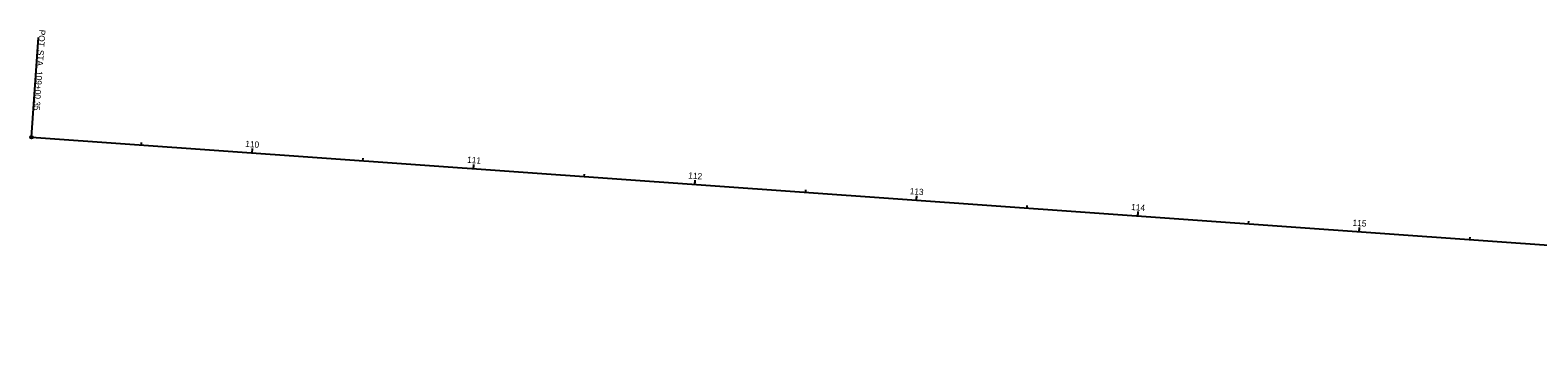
# Model space of a CAD drawing. Extents: x 1898401 to 1901169, y 703131 to 703379.
# Drawn here: x 1898401 to 1899080, y 703230 to 703379 of the extents above; entities that cross this region are included whole.
import ezdxf

# ---------------------------------------------------------------- set-up
doc = ezdxf.new("R2010")
doc.units = 0
for name, color, linetype in [('RW_X_CL', 7, 'Continuous'), ('RW_X_CL_1000_Cardinal_Points', 7, 'Continuous'), ('RW_X_CL_1000_Stations', 7, 'Continuous'), ('RW_X_CL_100_Cardinal_Points', 7, 'Continuous'), ('RW_X_CL_100_Stations', 7, 'Continuous'), ('RW_X_CL_500_Cardinal_Points', 7, 'Continuous'), ('RW_X_CL_500_Stations', 7, 'Continuous')]:
    doc.layers.add(name, color=color, linetype=linetype)

msp = doc.modelspace()

# ---------------------------------------------------------------- linework, layer by layer
at = {"layer": 'RW_X_CL'}
msp.add_line((1898401.58, 703330.4), (1899815.76, 703229.84), dxfattribs=at)
at = {"layer": 'RW_X_CL_1000_Cardinal_Points'}
msp.add_line((1898401.58, 703330.4), (1898404.77, 703375.29), dxfattribs=at)
msp.add_circle((1898401.58, 703330.4), 0.6, dxfattribs=at)
at = {"layer": 'RW_X_CL_1000_Stations'}
for p, q in [((1898500.98, 703323.33), (1898501.12, 703325.33)), ((1898999.72, 703287.87), (1898999.81, 703289.07))]:
    msp.add_line(p, q, dxfattribs=at)
at = {"layer": 'RW_X_CL_100_Cardinal_Points'}
msp.add_line((1898401.58, 703330.4), (1898404.77, 703375.29), dxfattribs=at)
msp.add_circle((1898401.58, 703330.4), 0.6, dxfattribs=at)
at = {"layer": 'RW_X_CL_100_Stations'}
for p, q in [((1898451.11, 703326.88), (1898451.19, 703328.08)), ((1898500.98, 703323.33), (1898501.12, 703325.33)), ((1898550.85, 703319.79), (1898550.94, 703320.98)), ((1898600.73, 703316.24), (1898600.87, 703318.24)), ((1898650.6, 703312.69), (1898650.69, 703313.89)), ((1898700.48, 703309.15), (1898700.62, 703311.14)), ((1898750.35, 703305.6), (1898750.44, 703306.8)), ((1898800.23, 703302.05), (1898800.37, 703304.05)), ((1898850.1, 703298.51), (1898850.18, 703299.7)), ((1898899.97, 703294.96), (1898900.12, 703296.96)), ((1898949.85, 703291.41), (1898949.93, 703292.61)), ((1898999.72, 703287.87), (1898999.86, 703289.86)), ((1899049.6, 703284.32), (1899049.68, 703285.52))]:
    msp.add_line(p, q, dxfattribs=at)
at = {"layer": 'RW_X_CL_500_Cardinal_Points'}
msp.add_line((1898401.58, 703330.4), (1898404.77, 703375.29), dxfattribs=at)
msp.add_circle((1898401.58, 703330.4), 0.6, dxfattribs=at)
at = {"layer": 'RW_X_CL_500_Stations'}
for p, q in [((1898500.98, 703323.33), (1898501.12, 703325.33)), ((1898600.73, 703316.24), (1898600.81, 703317.44)), ((1898700.48, 703309.15), (1898700.56, 703310.34)), ((1898800.23, 703302.05), (1898800.31, 703303.25)), ((1898899.97, 703294.96), (1898900.06, 703296.16)), ((1898999.72, 703287.87), (1898999.86, 703289.86))]:
    msp.add_line(p, q, dxfattribs=at)

# ---------------------------------------------------------------- texts
at = {"layer": 'RW_X_CL_1000_Cardinal_Points'}
for s, p in [('POT', (1898405.08, 703378.92)), (' STA. ', (1898404.51, 703370.89)), ('109+00.35', (1898403.76, 703360.34))]:
    msp.add_text(s, height=2.8, rotation=265.93252, dxfattribs=at).set_placement(p)
at = {"layer": 'RW_X_CL_1000_Stations'}
msp.add_text('110', height=2.8, rotation=355.93252, dxfattribs=at).set_placement((1898497.82, 703326.11))
at = {"layer": 'RW_X_CL_100_Cardinal_Points'}
for s, p in [('POT', (1898405.08, 703378.92)), (' STA. ', (1898404.51, 703370.89)), ('109+00.35', (1898403.76, 703360.34))]:
    msp.add_text(s, height=2.8, rotation=265.93252, dxfattribs=at).set_placement(p)
at = {"layer": 'RW_X_CL_100_Stations'}
for s, p in [('110', (1898497.82, 703326.11)), ('111', (1898597.76, 703318.96)), ('112', (1898697.38, 703311.87)), ('113', (1898797.14, 703304.82)), ('114', (1898896.89, 703297.7)), ('115', (1898996.61, 703290.64))]:
    msp.add_text(s, height=2.8, rotation=355.93252, dxfattribs=at).set_placement(p)
at = {"layer": 'RW_X_CL_500_Cardinal_Points'}
for s, p in [('POT', (1898405.08, 703378.92)), (' STA. ', (1898404.51, 703370.89)), ('109+00.35', (1898403.76, 703360.34))]:
    msp.add_text(s, height=2.8, rotation=265.93252, dxfattribs=at).set_placement(p)
at = {"layer": 'RW_X_CL_500_Stations'}
for s, p in [('110', (1898497.82, 703326.11)), ('115', (1898996.61, 703290.64))]:
    msp.add_text(s, height=2.8, rotation=355.93252, dxfattribs=at).set_placement(p)

doc.saveas('drawing.dxf')
